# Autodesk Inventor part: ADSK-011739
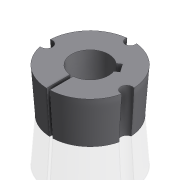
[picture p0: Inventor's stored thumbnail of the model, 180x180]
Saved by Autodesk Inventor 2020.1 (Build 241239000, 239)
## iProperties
Created: 2000-02
Part Number: ADSK-011739
Material: Pearson HRS
Document SubType Name: Modeling
Designer: glanglot
Density: 7.83 g/cm^3
Appearance: Métal - Acier
Mass: 1391.74 g
Surface Area: 278.815 cm^2
Volume: 177.745 cm^3
Control State: 0
Checked Out: False
Master: False
Shininess: 0.0
Length Units: 11269
Angle Units: 11279
Time Units: 11290
Mass Units: 11283
Length Display Precision: 3
Angle Display Precision: 2
Compacted: True
Dimensions: 85,9x44,5x85,7 mm
Mass: 1,392 kg
Density: 0.0
Volumn: 0.0
Area: 0.0
PropertySet Name: Model Information
Author: glanglot
Revision Number: -
Title: ADSK-011739
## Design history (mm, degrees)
node "Solide1"
  node "Revolution1" dims "d4" = 90 deg
  node "Extrusion1" dims "d10" = 25.4, "d11" = 0
  node "Hole1" dims "d12" = 12, "d13" = 9.525, "d14" = 6.35, "d15" = 60 deg, "d16" = 19.05, "d17" = 118 deg, "d30" = 6
  node "Hole2" dims "d18" = 10.2, "d19" = 9.525, "d20" = 6.35, "d21" = 60 deg, "d22" = 32.3, "d23" = 118 deg, "d31" = 24
  node "Extrusion2" dims "d28" = 25.4, "d29" = 0
sketch "Sketch1"
  geometry: L1 (-51.6, 0)-(8.6, 0) reference; L2 (0, 53.4)-(0, -8.9) reference; L3 (-19, 44.5)-(-43, 44.5); L4 (-43, 44.5)-(-39.888, 0); L5 (-39.888, 0)-(-19, 0); L6 (-19, 44.5)-(-19, 0); 1 further point
  constraints: 8 end point, 2 perpendicular, 2 point on line
  dimensions: "d0" = 44.5 distance between parallel lines of L1 L3; "d1" = 19 distance between parallel lines of L6 L2; "d2" = 43 distance from line of L3.end L2; "d3" = 94 deg angle of L5 L4
sketch "Sketch2"
  geometry: L1 (0, 0)-(-41.093, -3.595); L2 (0, 0)-(41.093, -3.595); L3 (0, 60.2)-(0, -60.2) reference; L4 (60.2, 0)-(-60.2, 0) reference; L5 (0, 0)-(0, 41.25); L6 (-1.6, -42.97)-(-1.6, -18.933); L7 (1.6, -18.933)-(1.6, -42.97); L8 (12.147, 14.61)-(15.973, 17.288); L9 (15.973, 17.288)-(21.708, 9.096); L10 (21.708, 9.096)-(17.883, 6.418); L11 (18.84, 13.192)-(0, 0); A1 r 19 centre (0, 0) between (-1.6, -18.933) and (1.6, -18.933) reference; A2 r 43 centre (0, 0) between (1.6, -42.97) and (-1.6, -42.97) reference; A3 r 41.25 centre (0, 0) between (-41.093, -3.595) and (41.093, -3.595); 3 further points
  constraints: 18 end point, 9 point on circle, 4 coincident, 3 parallel, 2 perpendicular, 1 centre point, 1 midpoint, 1 point on line
  dimensions: "d5" = 82.5 diameter of A3; "d6" = 5 deg angle of L1 L4; "d7" = 5 deg angle of L4 L2; "d8" = 1.6 distance between parallel lines of L3 L6 (= d9); "d9" = 1.6 distance between parallel lines of L7 L3; "d25" = 23 distance of L11.start L1.start; "d26" = 55 deg angle of L11 L5; "d27" = 10 distance between parallel lines of L10 L8
workplane "Arbeitsebene1"
node "Corps solides"
node "Corps surfaciques"
other parameters: "d32" = 90 deg
